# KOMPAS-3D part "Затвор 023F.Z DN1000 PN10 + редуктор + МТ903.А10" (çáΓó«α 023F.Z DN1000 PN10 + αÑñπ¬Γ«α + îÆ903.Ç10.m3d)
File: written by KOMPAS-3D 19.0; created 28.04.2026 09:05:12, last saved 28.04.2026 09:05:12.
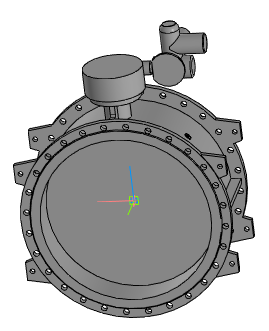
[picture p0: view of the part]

Document properties: Полное имя файла: ..\..\Затвор 023F.Z DN400-DN1600 + редуктор + МТ903\Затвор 023F.Z DN1000 PN10 + редуктор + МТ903.А10.a3d

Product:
- Part/product: Затвор 023F.Z DN1000 PN10 + редуктор + МТ903.А10
    Масса: 1389.85

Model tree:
1. Операция без истории:1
